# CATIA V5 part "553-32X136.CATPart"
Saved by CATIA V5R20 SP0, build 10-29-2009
Part number: 553-32X136
Definition: NONE
Nomenclature: 553-32X136
Source: Unknown
Description: 553-32X136
Bounding box of the stored display mesh (mm): x 0 to 136, y -23.5 to 23.5, z -23.5 to 23.5
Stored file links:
  C:\Users\Utente\Desktop\IO LAVORO\3D X SITO CF\X SITO\PLASTICA\553\553-32X136.CATPart
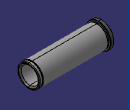
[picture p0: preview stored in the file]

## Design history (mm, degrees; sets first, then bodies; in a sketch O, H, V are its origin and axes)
Body1 "553-32X136" (main body)
  Solid1: solid without history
